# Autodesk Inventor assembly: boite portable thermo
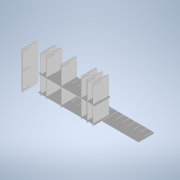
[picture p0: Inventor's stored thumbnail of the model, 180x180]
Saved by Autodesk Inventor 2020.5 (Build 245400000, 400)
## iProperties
Created: 2022-09
Part Number: boite portable thermo
Document SubType Name: Assembly
Designer: mel
Author: mel
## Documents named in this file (3)
- D:\travail\année 2022-2023\PP\boite portable thermo.iam
- D:\travail\année 2022-2023\PP\prépa thermo gd côté.ipt
- D:\travail\année 2022-2023\PP\prépa thermo petit côté.ipt
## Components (10 placed, 2 different names)
1. prépa thermo gd côté:1 — Affleurement:1, Placage:1, Affleurement:2, Affleurement:3, Affleurement:4, Affleurement:5, Affleurement:6, Affleurement:7, Affleurement:8, Placage:2, Placage:3, Placage:6, Placage:7, Placage:8, Placage:9, Placage:10, Placage:11, Placage:12
2. prépa thermo petit côté:1 — Affleurement:1, Placage:1, Affleurement:2, Affleurement:8, Placage:4, Affleurement:9, Placage:5
3. prépa thermo gd côté:2
4. prépa thermo gd côté:3 — Placage:4, Affleurement:9, Placage:5
5. prépa thermo petit côté:2
6. prépa thermo petit côté:3 — Affleurement:5, Placage:7, Placage:10
7. prépa thermo petit côté:4 — Affleurement:4, Placage:6
8. prépa thermo petit côté:5 — Affleurement:3, Placage:2, Placage:3
9. prépa thermo petit côté:6 — Affleurement:7, Placage:11, Placage:12
10. prépa thermo petit côté:7 — Affleurement:6, Placage:8, Placage:9
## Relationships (21: Mate 12, Flush 9)
- Affleurement:1 [Flush]: prépa thermo gd côté:1 ↔ prépa thermo petit côté:1
- Placage:1 [Mate]: prépa thermo gd côté:1 ↔ prépa thermo petit côté:1
- Affleurement:2 [Flush]: prépa thermo gd côté:1 ↔ prépa thermo petit côté:1
- Affleurement:3 [Flush]: prépa thermo gd côté:1 ↔ prépa thermo petit côté:5
- Affleurement:4 [Flush]: prépa thermo gd côté:1 ↔ prépa thermo petit côté:4
- Affleurement:5 [Flush]: prépa thermo gd côté:1 ↔ prépa thermo petit côté:3
- Affleurement:6 [Flush]: prépa thermo gd côté:1 ↔ prépa thermo petit côté:7
- Affleurement:7 [Flush]: prépa thermo gd côté:1 ↔ prépa thermo petit côté:6
- Affleurement:8 [Flush]: prépa thermo gd côté:1 ↔ prépa thermo petit côté:1
- Placage:2 [Mate]: prépa thermo gd côté:1 ↔ prépa thermo petit côté:5
- Placage:3 [Mate]: prépa thermo gd côté:1 ↔ prépa thermo petit côté:5
- Placage:4 [Mate]: prépa thermo petit côté:1 ↔ prépa thermo gd côté:3
- Affleurement:9 [Flush]: prépa thermo petit côté:1 ↔ prépa thermo gd côté:3
- Placage:5 [Mate]: prépa thermo petit côté:1 ↔ prépa thermo gd côté:3
- Placage:6 [Mate]: prépa thermo gd côté:1 ↔ prépa thermo petit côté:4
- Placage:7 [Mate]: prépa thermo gd côté:1 ↔ prépa thermo petit côté:3
- Placage:8 [Mate]: prépa thermo gd côté:1 ↔ prépa thermo petit côté:7
- Placage:9 [Mate]: prépa thermo gd côté:1 ↔ prépa thermo petit côté:7
- Placage:10 [Mate]: prépa thermo gd côté:1 ↔ prépa thermo petit côté:3
- Placage:11 [Mate]: prépa thermo gd côté:1 ↔ prépa thermo petit côté:6
- Placage:12 [Mate]: prépa thermo gd côté:1 ↔ prépa thermo petit côté:6
